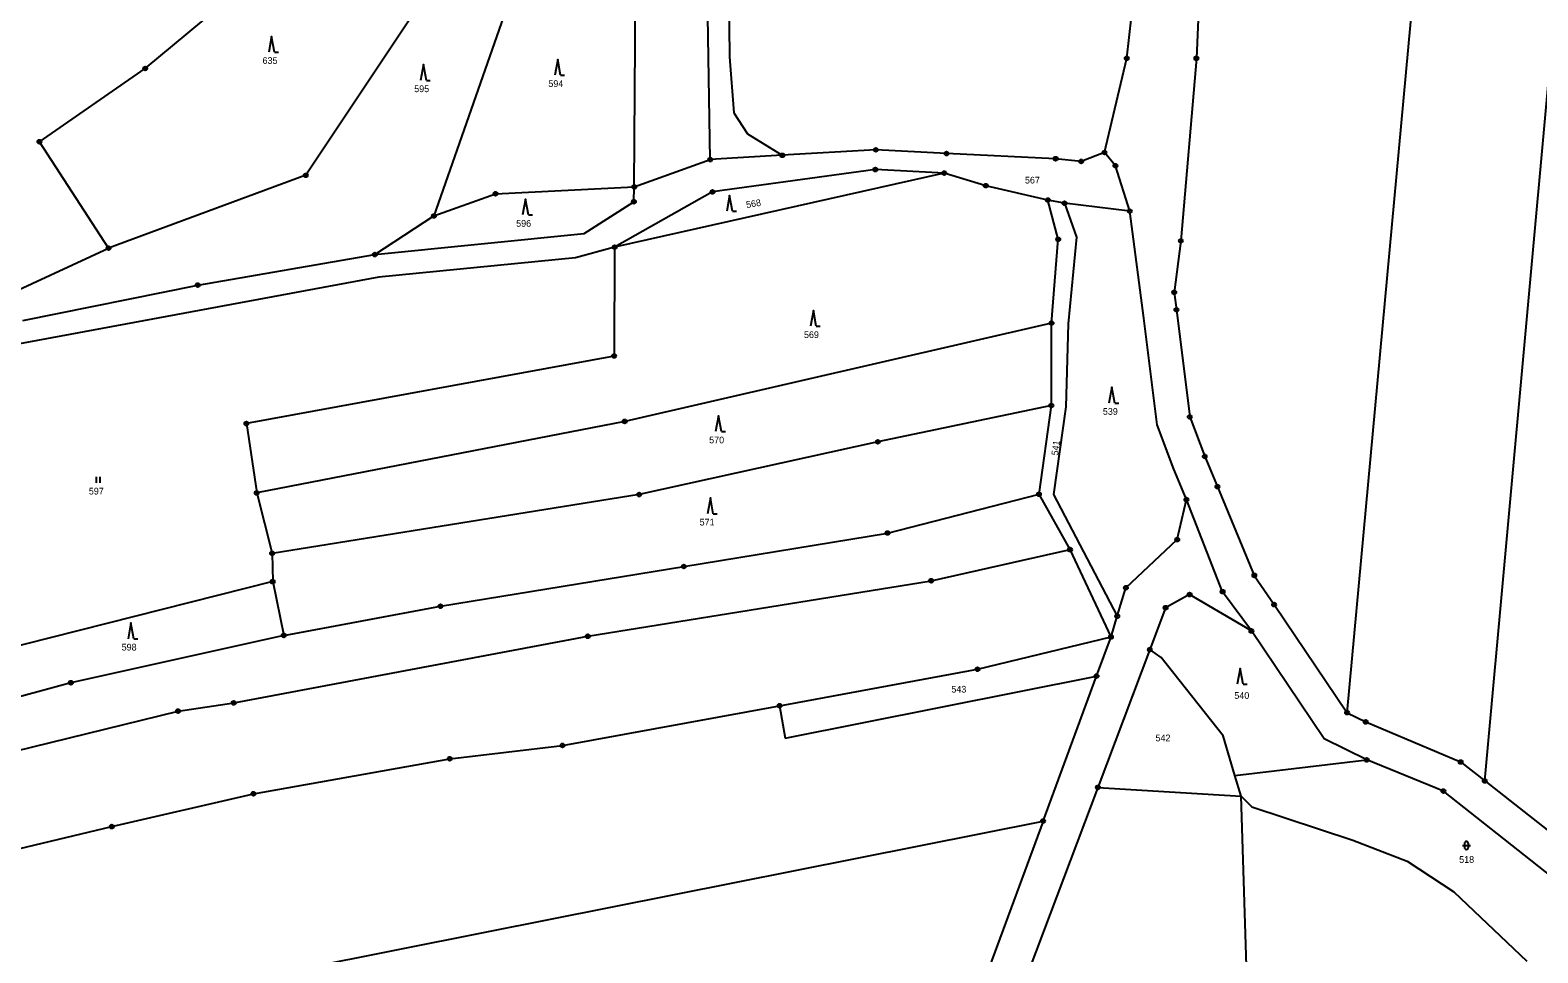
# Model space of a CAD drawing. Extents: x -719614 to -717765, y -1095834 to -1093862.
# Drawn here: x -719304.3 to -718922.3, y -1095165.2 to -1094931.3 of the extents above; entities that cross this region are included whole.
import ezdxf
from ezdxf.enums import TextEntityAlignment as Align

# ---------------------------------------------------------------- set-up
doc = ezdxf.new("R2010")
doc.units = 0
doc.header["$LTSCALE"] = 0.68
for name, color, linetype, lineweight in [('1', 7, 'Continuous', 25), ('3', 7, 'Continuous', 25), ('8', 7, 'Continuous', 25)]:
    doc.layers.add(name, color=color, linetype=linetype, lineweight=lineweight)
doc.layers.add('2', color=7, linetype='Continuous')

msp = doc.modelspace()

# ---------------------------------------------------------------- linework, layer by layer
at = {"layer": '1'}
for p, q in [((-719026.5, -1094938.4), (-719019.73, -1094878.83)), ((-719151.27, -1094971), (-719150.67, -1094885.71)), ((-719132.03, -1094964.06), (-719133.36, -1094885.81)), ((-719127.69, -1094887.54), (-719127.19, -1094937.98)), ((-719006.63, -1094888.88), (-719008.86, -1094938.4)), ((-719190.38, -1094901.7), (-719234.51, -1094968.06)), ((-719275.18, -1094940.98), (-719253.39, -1094922.8)), ((-718970.67, -1095104.3), (-718953.77, -1094920.49)), ((-719183.81, -1094926.16), (-719202.06, -1094978.37)), ((-719127.19, -1094937.98), (-719126.09, -1094952.25)), ((-719032.14, -1094962.28), (-719026.5, -1094938.4)), ((-719008.86, -1094938.4), (-719012.8, -1094984.67)), ((-719302, -1094959.54), (-719275.18, -1094940.98)), ((-718935.78, -1095121.61), (-718919.54, -1094943.34)), ((-719126.09, -1094952.25), (-719122.56, -1094957.53)), ((-719122.56, -1094957.53), (-719113.78, -1094962.99)), ((-719284.47, -1094986.53), (-719302, -1094959.54)), ((-719090.07, -1094961.6), (-719113.78, -1094962.99)), ((-719072.18, -1094962.54), (-719090.07, -1094961.6)), ((-719151.27, -1094971), (-719132.03, -1094964.06)), ((-719113.78, -1094962.99), (-719132.03, -1094964.06)), ((-719044.51, -1094963.85), (-719072.18, -1094962.54)), ((-719038.04, -1094964.54), (-719044.51, -1094963.85)), ((-719032.14, -1094962.28), (-719038.04, -1094964.54)), ((-719029.36, -1094965.64), (-719032.14, -1094962.28)), ((-719025.72, -1094977.15), (-719029.36, -1094965.64)), ((-719234.51, -1094968.06), (-719284.47, -1094986.53)), ((-719072.74, -1094967.51), (-719156.25, -1094986.28)), ((-719090.19, -1094966.6), (-719131.45, -1094972.27)), ((-719072.74, -1094967.51), (-719090.19, -1094966.6)), ((-719062.21, -1094970.69), (-719072.74, -1094967.51)), ((-719202.06, -1094978.37), (-719186.43, -1094972.73)), ((-719186.43, -1094972.73), (-719151.27, -1094971)), ((-719131.45, -1094972.27), (-719156.25, -1094986.28)), ((-719151.38, -1094974.75), (-719151.27, -1094971)), ((-719046.47, -1094974.35), (-719062.21, -1094970.69)), ((-719164, -1094982.8), (-719151.38, -1094974.75)), ((-719042.26, -1094975.14), (-719046.47, -1094974.35)), ((-719043.87, -1094984.29), (-719046.47, -1094974.35)), ((-719025.72, -1094977.15), (-719042.26, -1094975.14)), ((-719042.26, -1094975.14), (-719039.21, -1094983.78)), ((-719022.19, -1095004.29), (-719025.72, -1094977.15)), ((-719217.02, -1094988.16), (-719202.06, -1094978.37)), ((-719217.02, -1094988.16), (-719164, -1094982.8)), ((-719045.55, -1095005.53), (-719043.87, -1094984.29)), ((-719039.21, -1094983.78), (-719041.37, -1095005.75)), ((-719012.8, -1094984.67), (-719014.47, -1094997.74)), ((-719314.64, -1095000.48), (-719284.47, -1094986.53)), ((-719261.88, -1094995.89), (-719217.02, -1094988.16)), ((-719166.21, -1094988.99), (-719216.01, -1094993.9)), ((-719156.25, -1094986.28), (-719166.21, -1094988.99)), ((-719156.25, -1094986.28), (-719156.38, -1095013.87)), ((-719216.01, -1094993.9), (-719336.16, -1095016.2)), ((-719306.22, -1095004.89), (-719261.88, -1094995.89)), ((-719014.47, -1094997.74), (-719013.9, -1095002.14)), ((-719018.83, -1095031.35), (-719022.19, -1095004.29)), ((-719013.9, -1095002.14), (-719010.52, -1095029.3)), ((-719045.55, -1095005.53), (-719153.7, -1095030.47)), ((-719045.6, -1095026.42), (-719045.55, -1095005.53)), ((-719041.37, -1095005.75), (-719041.9, -1095026.73)), ((-719156.38, -1095013.87), (-719249.57, -1095031)), ((-719045.6, -1095026.42), (-719089.57, -1095035.63)), ((-719048.73, -1095048.91), (-719045.6, -1095026.42)), ((-719041.9, -1095026.73), (-719045.06, -1095049.01)), ((-719249.57, -1095031), (-719246.95, -1095048.57)), ((-719153.7, -1095030.47), (-719246.95, -1095048.57)), ((-719010.52, -1095029.3), (-719006.72, -1095039.34)), ((-719014.59, -1095042.57), (-719018.83, -1095031.35)), ((-719089.57, -1095035.63), (-719150.05, -1095048.99)), ((-719006.72, -1095039.34), (-719003.53, -1095047)), ((-719011.38, -1095050.27), (-719014.59, -1095042.57)), ((-719246.95, -1095048.57), (-719243.03, -1095063.91)), ((-719150.05, -1095048.99), (-719243.03, -1095063.91)), ((-719087.11, -1095058.75), (-719048.73, -1095048.91)), ((-719040.87, -1095062.96), (-719048.73, -1095048.91)), ((-719045.06, -1095049.01), (-719028.9, -1095079.85)), ((-719003.53, -1095047), (-718994.18, -1095069.49)), ((-719013.71, -1095060.42), (-719011.38, -1095050.27)), ((-719002.21, -1095073.62), (-719011.38, -1095050.27)), ((-719138.71, -1095067.24), (-719087.11, -1095058.75)), ((-719026.71, -1095072.64), (-719013.71, -1095060.42)), ((-719243.03, -1095063.91), (-719242.89, -1095071.07)), ((-719076.03, -1095070.84), (-719040.87, -1095062.96)), ((-719030.49, -1095085.11), (-719040.87, -1095062.96)), ((-719200.38, -1095077.3), (-719138.71, -1095067.24)), ((-719242.89, -1095071.07), (-719322.72, -1095091.26)), ((-719242.89, -1095071.07), (-719240.09, -1095084.7)), ((-719163.07, -1095084.93), (-719076.03, -1095070.84)), ((-719028.9, -1095079.85), (-719026.71, -1095072.64)), ((-718994.18, -1095069.49), (-718989.17, -1095076.9)), ((-719010.57, -1095074.35), (-719016.65, -1095077.69)), ((-718994.92, -1095083.58), (-719010.57, -1095074.35)), ((-718994.92, -1095083.58), (-719002.21, -1095073.62)), ((-719240.09, -1095084.7), (-719200.38, -1095077.3)), ((-719030.49, -1095085.11), (-719028.9, -1095079.85)), ((-719016.65, -1095077.69), (-719020.65, -1095088.31)), ((-718989.17, -1095076.9), (-718970.67, -1095104.3)), ((-718976.46, -1095110.91), (-718994.92, -1095083.58)), ((-719240.09, -1095084.7), (-719294.02, -1095096.7)), ((-719252.77, -1095101.82), (-719163.07, -1095084.93)), ((-719064.31, -1095093.29), (-719030.49, -1095085.11)), ((-719034.15, -1095095.03), (-719030.49, -1095085.11)), ((-719020.65, -1095088.31), (-719033.81, -1095123.24)), ((-719017.75, -1095090.34), (-719020.65, -1095088.31)), ((-719002.07, -1095110.18), (-719017.75, -1095090.34)), ((-719114.46, -1095102.55), (-719064.31, -1095093.29)), ((-719113.05, -1095110.74), (-719034.15, -1095095.03)), ((-719047.7, -1095131.78), (-719034.15, -1095095.03)), ((-719294.02, -1095096.7), (-719318.93, -1095103.46)), ((-719266.87, -1095103.89), (-719252.77, -1095101.82)), ((-719169.45, -1095112.61), (-719114.46, -1095102.55)), ((-719114.46, -1095102.55), (-719113.05, -1095110.74)), ((-719325.05, -1095118.17), (-719266.87, -1095103.89)), ((-718970.67, -1095104.3), (-718965.95, -1095106.64)), ((-718965.95, -1095106.64), (-718941.9, -1095116.8)), ((-718999.08, -1095120.2), (-719002.07, -1095110.18)), ((-718965.69, -1095116.27), (-718976.46, -1095110.91)), ((-719198.03, -1095115.99), (-719169.45, -1095112.61)), ((-719247.78, -1095124.86), (-719198.03, -1095115.99)), ((-718999.08, -1095120.2), (-718965.69, -1095116.27)), ((-718946.27, -1095124.18), (-718965.69, -1095116.27)), ((-718941.9, -1095116.8), (-718935.78, -1095121.61)), ((-718997.51, -1095125.46), (-718999.08, -1095120.2)), ((-718935.78, -1095121.61), (-718913.68, -1095138.98)), ((-719283.67, -1095133.19), (-719247.78, -1095124.86)), ((-719033.81, -1095123.24), (-719062.73, -1095199.98)), ((-719033.81, -1095123.24), (-718997.51, -1095125.46)), ((-718993, -1095270.99), (-718997.51, -1095125.46)), ((-718997.51, -1095125.46), (-718994.81, -1095128.17)), ((-718906.1, -1095155.97), (-718946.27, -1095124.18)), ((-718994.81, -1095128.17), (-718969.2, -1095136.64)), ((-719334.42, -1095145.22), (-719283.67, -1095133.19)), ((-719188.64, -1095159.84), (-719047.7, -1095131.78)), ((-719047.7, -1095131.78), (-719061.31, -1095168.69)), ((-718969.2, -1095136.64), (-718955.43, -1095141.92)), ((-718955.43, -1095141.92), (-718943.6, -1095149.69)), ((-718943.6, -1095149.69), (-718925.14, -1095167.33)), ((-719369.21, -1095195.79), (-719188.64, -1095159.84))]:
    msp.add_line(p, q, dxfattribs=at)
at = {"layer": '3'}
for p, q in [((-719242.41, -1094936.84), (-719241.414, -1094936.84)), ((-719169.93, -1094942.67), (-719168.934, -1094942.67)), ((-719203.95, -1094943.99), (-719202.954, -1094943.99)), ((-719126.36, -1094977.15), (-719125.364, -1094977.15)), ((-719178.08, -1094978.12), (-719177.084, -1094978.12)), ((-719105.16, -1095006.34), (-719104.164, -1095006.34)), ((-719029.5, -1095025.8), (-719028.504, -1095025.8)), ((-719129.16, -1095033.02), (-719128.164, -1095033.02)), ((-719287.571, -1095046), (-719287.571, -1095044.5)), ((-719286.57, -1095046), (-719286.57, -1095044.5)), ((-719131.25, -1095053.86), (-719130.254, -1095053.86)), ((-719278.05, -1095085.56), (-719277.054, -1095085.56)), ((-718996.99, -1095097.11), (-718995.994, -1095097.11)), ((-718941.441, -1095137.951), (-718939.439, -1095137.951)), ((-718940.941, -1095137.451), (-718940.941, -1095138.452)), ((-718939.939, -1095138.452), (-718939.939, -1095137.451))]:
    msp.add_line(p, q, dxfattribs=at)
for points in [[(-719242.41, -1094936.84), (-719243.16, -1094932.84), (-719243.91, -1094936.84)], [(-719169.93, -1094942.67), (-719170.68, -1094938.67), (-719171.43, -1094942.67)], [(-719203.95, -1094943.99), (-719204.7, -1094939.99), (-719205.45, -1094943.99)], [(-719126.36, -1094977.15), (-719127.11, -1094973.15), (-719127.86, -1094977.15)], [(-719178.08, -1094978.12), (-719178.83, -1094974.12), (-719179.58, -1094978.12)], [(-719105.16, -1095006.34), (-719105.91, -1095002.34), (-719106.66, -1095006.34)], [(-719029.5, -1095025.8), (-719030.25, -1095021.8), (-719031, -1095025.8)], [(-719129.16, -1095033.02), (-719129.91, -1095029.02), (-719130.66, -1095033.02)], [(-719131.25, -1095053.86), (-719132, -1095049.86), (-719132.75, -1095053.86)], [(-719278.05, -1095085.56), (-719278.8, -1095081.56), (-719279.55, -1095085.56)], [(-718996.99, -1095097.11), (-718997.74, -1095093.11), (-718998.49, -1095097.11)]]:
    msp.add_lwpolyline(points, dxfattribs=at)
for centre, start, end in [((-718940.44, -1095137.4509), 0, 180), ((-718940.44, -1095138.4509), 180, 359.98789)]:
    msp.add_arc(centre, 0.5, start, end, dxfattribs=at)
at = {"layer": '8'}
for centre, radius in [((-719026.5, -1094938.3999), 0.5), ((-719026.5, -1094938.3999), 0.0303), ((-719008.86, -1094938.3999), 0.5), ((-719008.86, -1094938.3999), 0.0303), ((-719275.18, -1094940.9799), 0.5), ((-719275.18, -1094940.9799), 0.0303), ((-719302, -1094959.5399), 0.5), ((-719302, -1094959.5399), 0.0303), ((-719090.07, -1094961.5999), 0.5), ((-719090.07, -1094961.5999), 0.0303), ((-719072.18, -1094962.5399), 0.5), ((-719032.14, -1094962.2799), 0.5), ((-719032.14, -1094962.2799), 0.0303), ((-719132.03, -1094964.0599), 0.5), ((-719132.03, -1094964.0599), 0.0303), ((-719113.78, -1094962.9899), 0.5), ((-719113.78, -1094962.9899), 0.0303), ((-719072.18, -1094962.5399), 0.0303), ((-719044.51, -1094963.8499), 0.5), ((-719044.51, -1094963.8499), 0.0303), ((-719038.04, -1094964.5399), 0.5), ((-719038.04, -1094964.5399), 0.0303), ((-719029.36, -1094965.6399), 0.5), ((-719029.36, -1094965.6399), 0.0303), ((-719234.51, -1094968.0599), 0.5), ((-719234.51, -1094968.0599), 0.0303), ((-719090.19, -1094966.5999), 0.5), ((-719090.19, -1094966.5999), 0.0303), ((-719072.74, -1094967.5099), 0.5), ((-719072.74, -1094967.5099), 0.0303), ((-719186.43, -1094972.7299), 0.5), ((-719186.43, -1094972.7299), 0.0303), ((-719151.27, -1094970.9999), 0.5), ((-719151.27, -1094970.9999), 0.0303), ((-719131.45, -1094972.2699), 0.5), ((-719131.45, -1094972.2699), 0.0303), ((-719062.21, -1094970.6899), 0.5), ((-719062.21, -1094970.6899), 0.0303), ((-719151.38, -1094974.7499), 0.5), ((-719151.38, -1094974.7499), 0.0303), ((-719046.47, -1094974.3499), 0.5), ((-719046.47, -1094974.3499), 0.0303), ((-719042.26, -1094975.1399), 0.5), ((-719042.26, -1094975.1399), 0.0303), ((-719025.72, -1094977.1499), 0.5), ((-719025.72, -1094977.1499), 0.0303), ((-719202.06, -1094978.3699), 0.5), ((-719202.06, -1094978.3699), 0.0303), ((-719043.87, -1094984.2899), 0.5), ((-719043.87, -1094984.2899), 0.0303), ((-719012.8, -1094984.6699), 0.5), ((-719012.8, -1094984.6699), 0.0303), ((-719284.47, -1094986.5299), 0.5), ((-719284.47, -1094986.5299), 0.0303), ((-719217.02, -1094988.1599), 0.5), ((-719217.02, -1094988.1599), 0.0303), ((-719156.25, -1094986.2799), 0.5), ((-719156.25, -1094986.2799), 0.0303), ((-719261.88, -1094995.8899), 0.5), ((-719261.88, -1094995.8899), 0.0303), ((-719014.47, -1094997.7399), 0.5), ((-719014.47, -1094997.7399), 0.0303), ((-719013.9, -1095002.1399), 0.5), ((-719013.9, -1095002.1399), 0.0303), ((-719045.55, -1095005.5299), 0.5), ((-719045.55, -1095005.5299), 0.0303), ((-719156.38, -1095013.8699), 0.5), ((-719156.38, -1095013.8699), 0.0303), ((-719045.6, -1095026.4199), 0.5), ((-719045.6, -1095026.4199), 0.0303), ((-719249.57, -1095030.9999), 0.5), ((-719249.57, -1095030.9999), 0.0303), ((-719153.7, -1095030.4699), 0.5), ((-719153.7, -1095030.4699), 0.0303), ((-719010.52, -1095029.2999), 0.5), ((-719010.52, -1095029.2999), 0.0303), ((-719089.57, -1095035.6299), 0.5), ((-719089.57, -1095035.6299), 0.0303), ((-719006.72, -1095039.3399), 0.5), ((-719006.72, -1095039.3399), 0.0303), ((-719246.95, -1095048.5699), 0.5), ((-719246.95, -1095048.5699), 0.0303), ((-719150.05, -1095048.9899), 0.5), ((-719150.05, -1095048.9899), 0.0303), ((-719048.73, -1095048.9099), 0.5), ((-719048.73, -1095048.9099), 0.0303), ((-719011.38, -1095050.2699), 0.5), ((-719003.53, -1095046.9999), 0.5), ((-719003.53, -1095046.9999), 0.0303), ((-719011.38, -1095050.2699), 0.0303), ((-719087.11, -1095058.7499), 0.5), ((-719087.11, -1095058.7499), 0.0303), ((-719013.71, -1095060.4199), 0.5), ((-719013.71, -1095060.4199), 0.0303), ((-719243.03, -1095063.9099), 0.5), ((-719243.03, -1095063.9099), 0.0303), ((-719040.87, -1095062.9599), 0.5), ((-719040.87, -1095062.9599), 0.0303), ((-719138.71, -1095067.2399), 0.5), ((-719138.71, -1095067.2399), 0.0303), ((-718994.18, -1095069.4899), 0.5), ((-719242.89, -1095071.0699), 0.5), ((-719242.89, -1095071.0699), 0.0303), ((-719076.03, -1095070.8399), 0.5), ((-719076.03, -1095070.8399), 0.0303), ((-719026.71, -1095072.6399), 0.5), ((-719026.71, -1095072.6399), 0.0303), ((-718994.18, -1095069.4899), 0.0303), ((-719200.38, -1095077.2999), 0.5), ((-719010.57, -1095074.3499), 0.5), ((-719010.57, -1095074.3499), 0.0303), ((-719002.21, -1095073.6199), 0.5), ((-719002.21, -1095073.6199), 0.0303), ((-718989.17, -1095076.8999), 0.5), ((-718989.17, -1095076.8999), 0.0303), ((-719200.38, -1095077.2999), 0.0303), ((-719028.9, -1095079.8499), 0.5), ((-719028.9, -1095079.8499), 0.0303), ((-719016.65, -1095077.6899), 0.5), ((-719016.65, -1095077.6899), 0.0303), ((-719240.09, -1095084.6999), 0.5), ((-719163.07, -1095084.9299), 0.5), ((-718994.92, -1095083.5799), 0.5), ((-718994.92, -1095083.5799), 0.0303), ((-719240.09, -1095084.6999), 0.0303), ((-719163.07, -1095084.9299), 0.0303), ((-719030.49, -1095085.1099), 0.5), ((-719030.49, -1095085.1099), 0.0303), ((-719020.65, -1095088.3099), 0.5), ((-719020.65, -1095088.3099), 0.0303), ((-719064.31, -1095093.2899), 0.5), ((-719064.31, -1095093.2899), 0.0303), ((-719034.15, -1095095.0299), 0.5), ((-719034.15, -1095095.0299), 0.0303), ((-719294.02, -1095096.6999), 0.5), ((-719294.02, -1095096.6999), 0.0303), ((-719266.87, -1095103.8899), 0.5), ((-719252.77, -1095101.8199), 0.5), ((-719252.77, -1095101.8199), 0.0303), ((-719114.46, -1095102.5499), 0.5), ((-719114.46, -1095102.5499), 0.0303), ((-719266.87, -1095103.8899), 0.0303), ((-718970.67, -1095104.2999), 0.5), ((-718970.67, -1095104.2999), 0.0303), ((-718965.95, -1095106.6399), 0.5), ((-718965.95, -1095106.6399), 0.0303), ((-719169.45, -1095112.6099), 0.5), ((-719169.45, -1095112.6099), 0.0303), ((-719198.03, -1095115.9899), 0.5), ((-719198.03, -1095115.9899), 0.0303), ((-718965.69, -1095116.2699), 0.5), ((-718965.69, -1095116.2699), 0.0303), ((-718941.9, -1095116.7999), 0.5), ((-718941.9, -1095116.7999), 0.0303), ((-718935.78, -1095121.6099), 0.5), ((-718935.78, -1095121.6099), 0.0303), ((-719247.78, -1095124.8599), 0.5), ((-719247.78, -1095124.8599), 0.0303), ((-719033.81, -1095123.2399), 0.5), ((-719033.81, -1095123.2399), 0.0303), ((-718946.27, -1095124.1799), 0.5), ((-718946.27, -1095124.1799), 0.0303), ((-719283.67, -1095133.1899), 0.5), ((-719283.67, -1095133.1899), 0.0303), ((-719047.7, -1095131.7799), 0.5), ((-719047.7, -1095131.7799), 0.0303)]:
    msp.add_circle(centre, radius, dxfattribs=at)

# ---------------------------------------------------------------- texts
at = {"layer": '2'}
for s, p in [('635', (-719243.569, -1094939.822)), ('595', (-719205.139, -1094946.972)), ('594', (-719171.159, -1094945.652)), ('567', (-719050.399, -1094970.132)), ('596', (-719179.309, -1094981.102)), ('569', (-719106.389, -1095009.322)), ('539', (-719030.659, -1095028.782)), ('570', (-719130.409, -1095036.002)), ('597', (-719287.579, -1095048.982)), ('571', (-719132.829, -1095056.842)), ('598', (-719279.269, -1095088.542)), ('543', (-719069.049, -1095099.202)), ('540', (-718997.349, -1095100.792)), ('542', (-719017.319, -1095111.542)), ('518', (-718940.379, -1095142.372))]:
    msp.add_text(s, height=1.7, dxfattribs=at).set_placement(p, align=Align.CENTER)
for s, rotation, p in [('568', 9, (-719120.941, -1094976.0755)), ('541', 82, (-719043.6604, -1095037.2983))]:
    msp.add_text(s, height=1.7, rotation=rotation, dxfattribs=at).set_placement(p, align=Align.CENTER)

doc.saveas('drawing.dxf')
